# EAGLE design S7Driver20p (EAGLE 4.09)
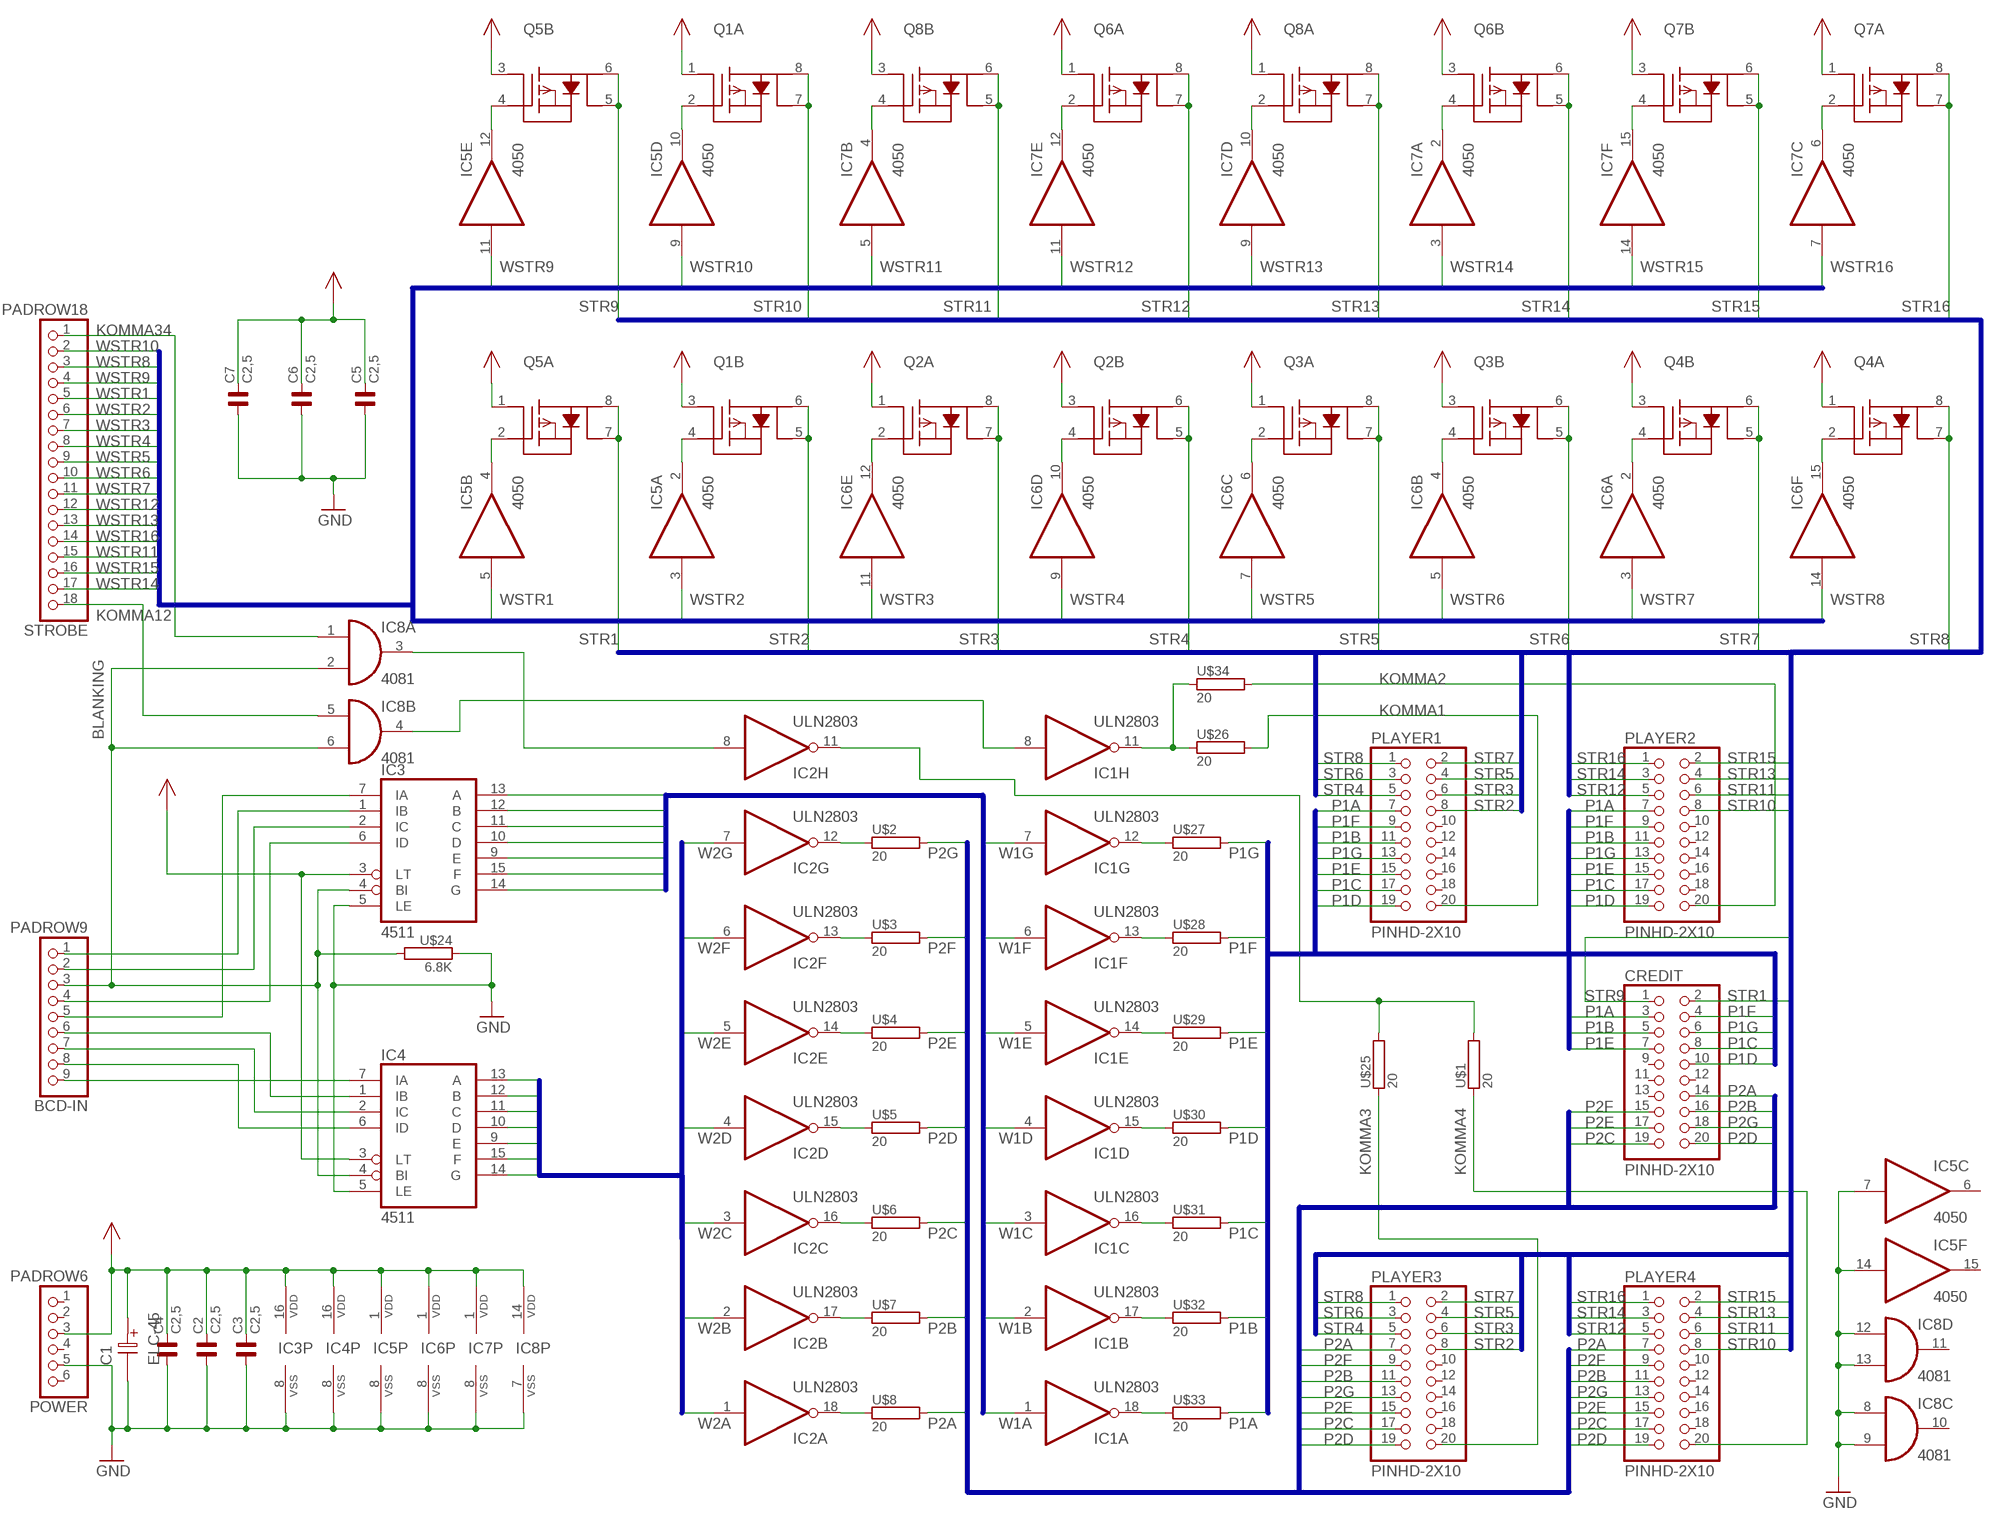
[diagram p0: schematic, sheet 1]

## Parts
BCD-IN  PADROW9  [PLATINE9]
C1  ELC-45  [E-45]
C2  C2,5  [C5B2,5]
C3  C2,5  [C5B2,5]
C4  C2,5  [C5B2,5]
C5  C2,5  [C5B2,5]
C6  C2,5  [C5B2,5]
C7  C2,5  [C5B2,5]
CREDIT  PINHD-2X10  [2X10]
IC1  ULN2803  [DIL18]
IC2  ULN2803  [DIL18]
IC3  4511  [DIL16]
IC4  4511  [DIL16]
IC5  4050  [DIL16]
IC6  4050  [DIL16]
IC7  4050  [DIL16]
IC8  4081  [DIL14]
PLAYER1  PINHD-2X10  [2X10]
PLAYER2  PINHD-2X10  [2X10]
PLAYER3  PINHD-2X10  [2X10]
PLAYER4  PINHD-2X10  [2X10]
POWER  PADROW6  [PLATINE6]
Q1  IRF7316  [SO-8]
Q2  IRF7316  [SO-8]
Q3  IRF7316  [SO-8]
Q4  IRF7316  [SO-8]
Q5  IRF7316  [SO-8]
Q6  IRF7316  [SO-8]
Q7  IRF7316  [SO-8]
Q8  IRF7316  [SO-8]
STROBE  PADROW18  [PLTINE18]
U$1  20  R1206  [0207/10]
U$2  20  R1206@2  [0207/15A]
U$3  20  R1206@2  [0207/15A]
U$4  20  R1206@2  [0207/15A]
U$5  20  R1206@2  [0207/15A]
U$6  20  R1206@2  [0207/15A]
U$7  20  R1206@2  [0207/15A]
U$8  20  R1206@2  [0207/15A]
U$24  6.8K  R1206@3  [0207/12A]
U$25  20  R1206  [0207/10]
U$26  20  R1206  [0207/10]
U$27  20  R1206  [0207/10]
U$28  20  R1206  [0207/10]
U$29  20  R1206  [0207/10]
U$30  20  R1206  [0207/10]
U$31  20  R1206  [0207/10]
U$32  20  R1206  [0207/10]
U$33  20  R1206  [0207/10]
U$34  20  R1206  [0207/10]

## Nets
BLANKING: BCD-IN.3 IC3.4(BI) IC4.4(BI) IC8.2(A:I1) IC8.6(B:I1) U$24.2
GND: C1.2 C2.1 C3.1 C4.1 C5.1 C6.1 C7.1 IC3.5(LE) IC3.8(VSS) IC4.5(LE) IC4.8(VSS) IC5.7(C:I) IC5.8(P:VSS) IC5.14(F:I) IC6.8(P:VSS) IC7.8(P:VSS) IC8.7(P:VSS) IC8.8(C:I0) IC8.9(C:I1) IC8.12(D:I0) IC8.13(D:I1) POWER.5 U$24.1
KOMMA1: PLAYER1.20 U$26.2
KOMMA2: PLAYER2.20 U$34.2
KOMMA3: PLAYER3.20 U$25.1
KOMMA4: PLAYER4.20 U$1.1
KOMMA12: IC8.5(B:I0) STROBE.18
KOMMA34: IC8.1(A:I0) STROBE.1
N$1: IC1.11(H:O) U$26.1 U$34.1
N$2: IC1.12(G:O) U$27.1
N$3: IC1.13(F:O) U$28.1
N$4: IC1.14(E:O) U$29.1
N$5: IC1.15(D:O) U$30.1
N$6: IC1.16(C:O) U$31.1
N$7: IC1.17(B:O) U$32.1
N$8: IC1.18(A:O) U$33.1
N$9: IC2.11(H:O) U$1.2 U$25.2
N$10: IC2.14(E:O) U$4.1
N$11: IC2.15(D:O) U$5.1
N$12: IC2.16(C:O) U$6.1
N$13: IC2.17(B:O) U$7.1
N$14: IC2.18(A:O) U$8.1
N$15: IC2.12(G:O) U$2.1
N$16: IC2.13(F:O) U$3.1
N$17: BCD-IN.2 IC3.2(IC)
N$18: BCD-IN.4 IC3.6(ID)
N$19: BCD-IN.5 IC3.7(IA)
N$20: BCD-IN.6 IC4.1(IB)
N$21: BCD-IN.7 IC4.2(IC)
N$22: BCD-IN.8 IC4.6(ID)
N$23: BCD-IN.9 IC4.7(IA)
N$24: IC1.8(H:I) IC8.4(B:O)
N$25: BCD-IN.1 IC3.1(IB)
N$26: IC5.12(E:O) Q5.4
N$27: IC7.2(A:O) Q6.4
N$28: IC5.10(D:O) Q1.2
N$30: IC7.15(F:O) Q7.4
N$31: IC7.4(B:O) Q8.4
N$33: IC7.12(E:O) Q6.2
N$34: IC5.4(B:O) Q5.2
N$35: IC5.2(A:O) Q1.4
N$36: IC6.12(E:O) Q2.2
N$37: IC7.6(C:O) Q7.2
N$38: IC6.10(D:O) Q2.4
N$39: IC7.10(D:O) Q8.2
N$40: IC6.6(C:O) Q3.2
N$44: IC6.4(B:O) Q3.4
N$46: IC6.2(A:O) Q4.4
N$48: IC2.8(H:I) IC8.3(A:O)
N$49: IC6.15(F:O) Q4.2
P1A: CREDIT.3 PLAYER1.7 PLAYER2.7 U$33.2
P1B: CREDIT.5 PLAYER1.11 PLAYER2.11 U$32.2
P1C: CREDIT.8 PLAYER1.17 PLAYER2.17 U$31.2
P1D: CREDIT.10 PLAYER1.19 PLAYER2.19 U$30.2
P1E: CREDIT.7 PLAYER1.15 PLAYER2.15 U$29.2
P1F: CREDIT.4 PLAYER1.9 PLAYER2.9 U$28.2
P1G: CREDIT.6 PLAYER1.13 PLAYER2.13 U$27.2
P2A: CREDIT.14 PLAYER3.7 PLAYER4.7 U$8.2
P2B: CREDIT.16 PLAYER3.11 PLAYER4.11 U$7.2
P2C: CREDIT.19 PLAYER3.17 PLAYER4.17 U$6.2
P2D: CREDIT.20 PLAYER3.19 PLAYER4.19 U$5.2
P2E: CREDIT.17 PLAYER3.15 PLAYER4.15 U$4.2
P2F: CREDIT.15 PLAYER3.9 PLAYER4.9 U$3.2
P2G: CREDIT.18 PLAYER3.13 PLAYER4.13 U$2.2
STR1: CREDIT.2 Q5.7 Q5.8
STR2: PLAYER1.8 PLAYER3.8 Q1.5 Q1.6
STR3: PLAYER1.6 PLAYER3.6 Q2.7 Q2.8
STR4: PLAYER1.5 PLAYER3.5 Q2.5 Q2.6
STR5: PLAYER1.4 PLAYER3.4 Q3.7 Q3.8
STR6: PLAYER1.3 PLAYER3.3 Q3.5 Q3.6
STR7: PLAYER1.2 PLAYER3.2 Q4.5 Q4.6
STR8: PLAYER1.1 PLAYER3.1 Q4.7 Q4.8
STR9: CREDIT.1 Q5.5 Q5.6
STR10: PLAYER2.8 PLAYER4.8 Q1.7 Q1.8
STR11: PLAYER2.6 PLAYER4.6 Q8.5 Q8.6
STR12: PLAYER2.5 PLAYER4.5 Q6.7 Q6.8
STR13: PLAYER2.4 PLAYER4.4 Q8.7 Q8.8
STR14: PLAYER2.3 PLAYER4.3 Q6.5 Q6.6
STR15: PLAYER2.2 PLAYER4.2 Q7.5 Q7.6
STR16: PLAYER2.1 PLAYER4.1 Q7.7 Q7.8
VCC: C1.1 C2.2 C3.2 C4.2 C5.2 C6.2 C7.2 IC3.3(LT) IC3.16(VDD) IC4.3(LT) IC4.16(VDD) IC5.1(P:VDD) IC6.1(P:VDD) IC7.1(P:VDD) IC8.14(P:VDD) POWER.3 Q1.1 Q1.3 Q2.1 Q2.3 Q3.1 Q3.3 Q4.1 Q4.3 Q5.1 Q5.3 Q6.1 Q6.3 Q7.1 Q7.3 Q8.1 Q8.3
W1A: IC1.1(A:I) IC3.13(A)
W1B: IC1.2(B:I) IC3.12(B)
W1C: IC1.3(C:I) IC3.11(C)
W1D: IC1.4(D:I) IC3.10(D)
W1E: IC1.5(E:I) IC3.9(E)
W1F: IC1.6(F:I) IC3.15(F)
W1G: IC1.7(G:I) IC3.14(G)
W2A: IC2.1(A:I) IC4.13(A)
W2B: IC2.2(B:I) IC4.12(B)
W2C: IC2.3(C:I) IC4.11(C)
W2D: IC2.4(D:I) IC4.10(D)
W2E: IC2.5(E:I) IC4.9(E)
W2F: IC2.6(F:I) IC4.15(F)
W2G: IC2.7(G:I) IC4.14(G)
WSTR1: IC5.5(B:I) STROBE.5
WSTR2: IC5.3(A:I) STROBE.6
WSTR3: IC6.11(E:I) STROBE.7
WSTR4: IC6.9(D:I) STROBE.8
WSTR5: IC6.7(C:I) STROBE.9
WSTR6: IC6.5(B:I) STROBE.10
WSTR7: IC6.3(A:I) STROBE.11
WSTR8: IC6.14(F:I) STROBE.3
WSTR9: IC5.11(E:I) STROBE.4
WSTR10: IC5.9(D:I) STROBE.2
WSTR11: IC7.5(B:I) STROBE.15
WSTR12: IC7.11(E:I) STROBE.12
WSTR13: IC7.9(D:I) STROBE.13
WSTR14: IC7.3(A:I) STROBE.17
WSTR15: IC7.14(F:I) STROBE.16
WSTR16: IC7.7(C:I) STROBE.14
Unconnected: CREDIT.9 CREDIT.11 CREDIT.12 CREDIT.13 IC1.10(CLAMP:CLAMP) IC2.10(CLAMP:CLAMP) IC5.6(C:O) IC5.15(F:O) IC8.10(C:O) IC8.11(D:O) PLAYER1.10 PLAYER1.12 PLAYER1.14 PLAYER1.16 PLAYER1.18 PLAYER2.10 PLAYER2.12 PLAYER2.14 PLAYER2.16 PLAYER2.18 PLAYER3.10 PLAYER3.12 PLAYER3.14 PLAYER3.16 PLAYER3.18 PLAYER4.10 PLAYER4.12 PLAYER4.14 PLAYER4.16 PLAYER4.18 POWER.1 POWER.2 POWER.4 POWER.6

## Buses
W2:W2A,W2B,W2C,W2D,W2E,W2F,W2G
W1:W1A,W1B,W1C,W1D,W1E,W1F,W1G
P1:P1A,P1B,P1C,P1D,P1E,P1F,P1G
P2:P2A,P2B,P2C,P2D,P2E,P2F,P2G
WSTR:WSTR1,WSTR2,WSTR3,WSTR4,WSTR5,WSTR6,WSTR7,WSTR8,WSTR9,WSTR10,WSTR11,WSTR12,WSTR13,WSTR14,WSTR15,WSTR16
STR:STR1,STR2,STR3,STR4,STR5,STR6,STR7,STR8,STR9,STR10,STR11,STR12,STR13,STR14,STR15,STR16

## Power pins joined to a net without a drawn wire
GND: IC1.9(GND:GND) IC2.9(GND:GND)

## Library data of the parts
BCD-IN = SPECIAL:PADROW9
C1 = DISCRETE:ELC-45
C2-C7 = CAP:C2,5
CREDIT PLAYER1-PLAYER4 = PINHEAD:PINHD-2X10
IC1 IC2 = SPECIAL:ULN2803
IC3 IC4 = 45XXSMD:4511
IC5-IC7 = 40XX:4050
IC8 = 40XXSMD:4081
POWER = SPECIAL:PADROW6
Q1-Q8 = Fari:IRF7316
STROBE = SPECIAL:PADROW18
U$1 U$25 U$34 = SPECIAL:R1206
U$2-U$8 = R:R1206@2
U$24 = R:R1206@3
U$26-U$33 = R:R1206

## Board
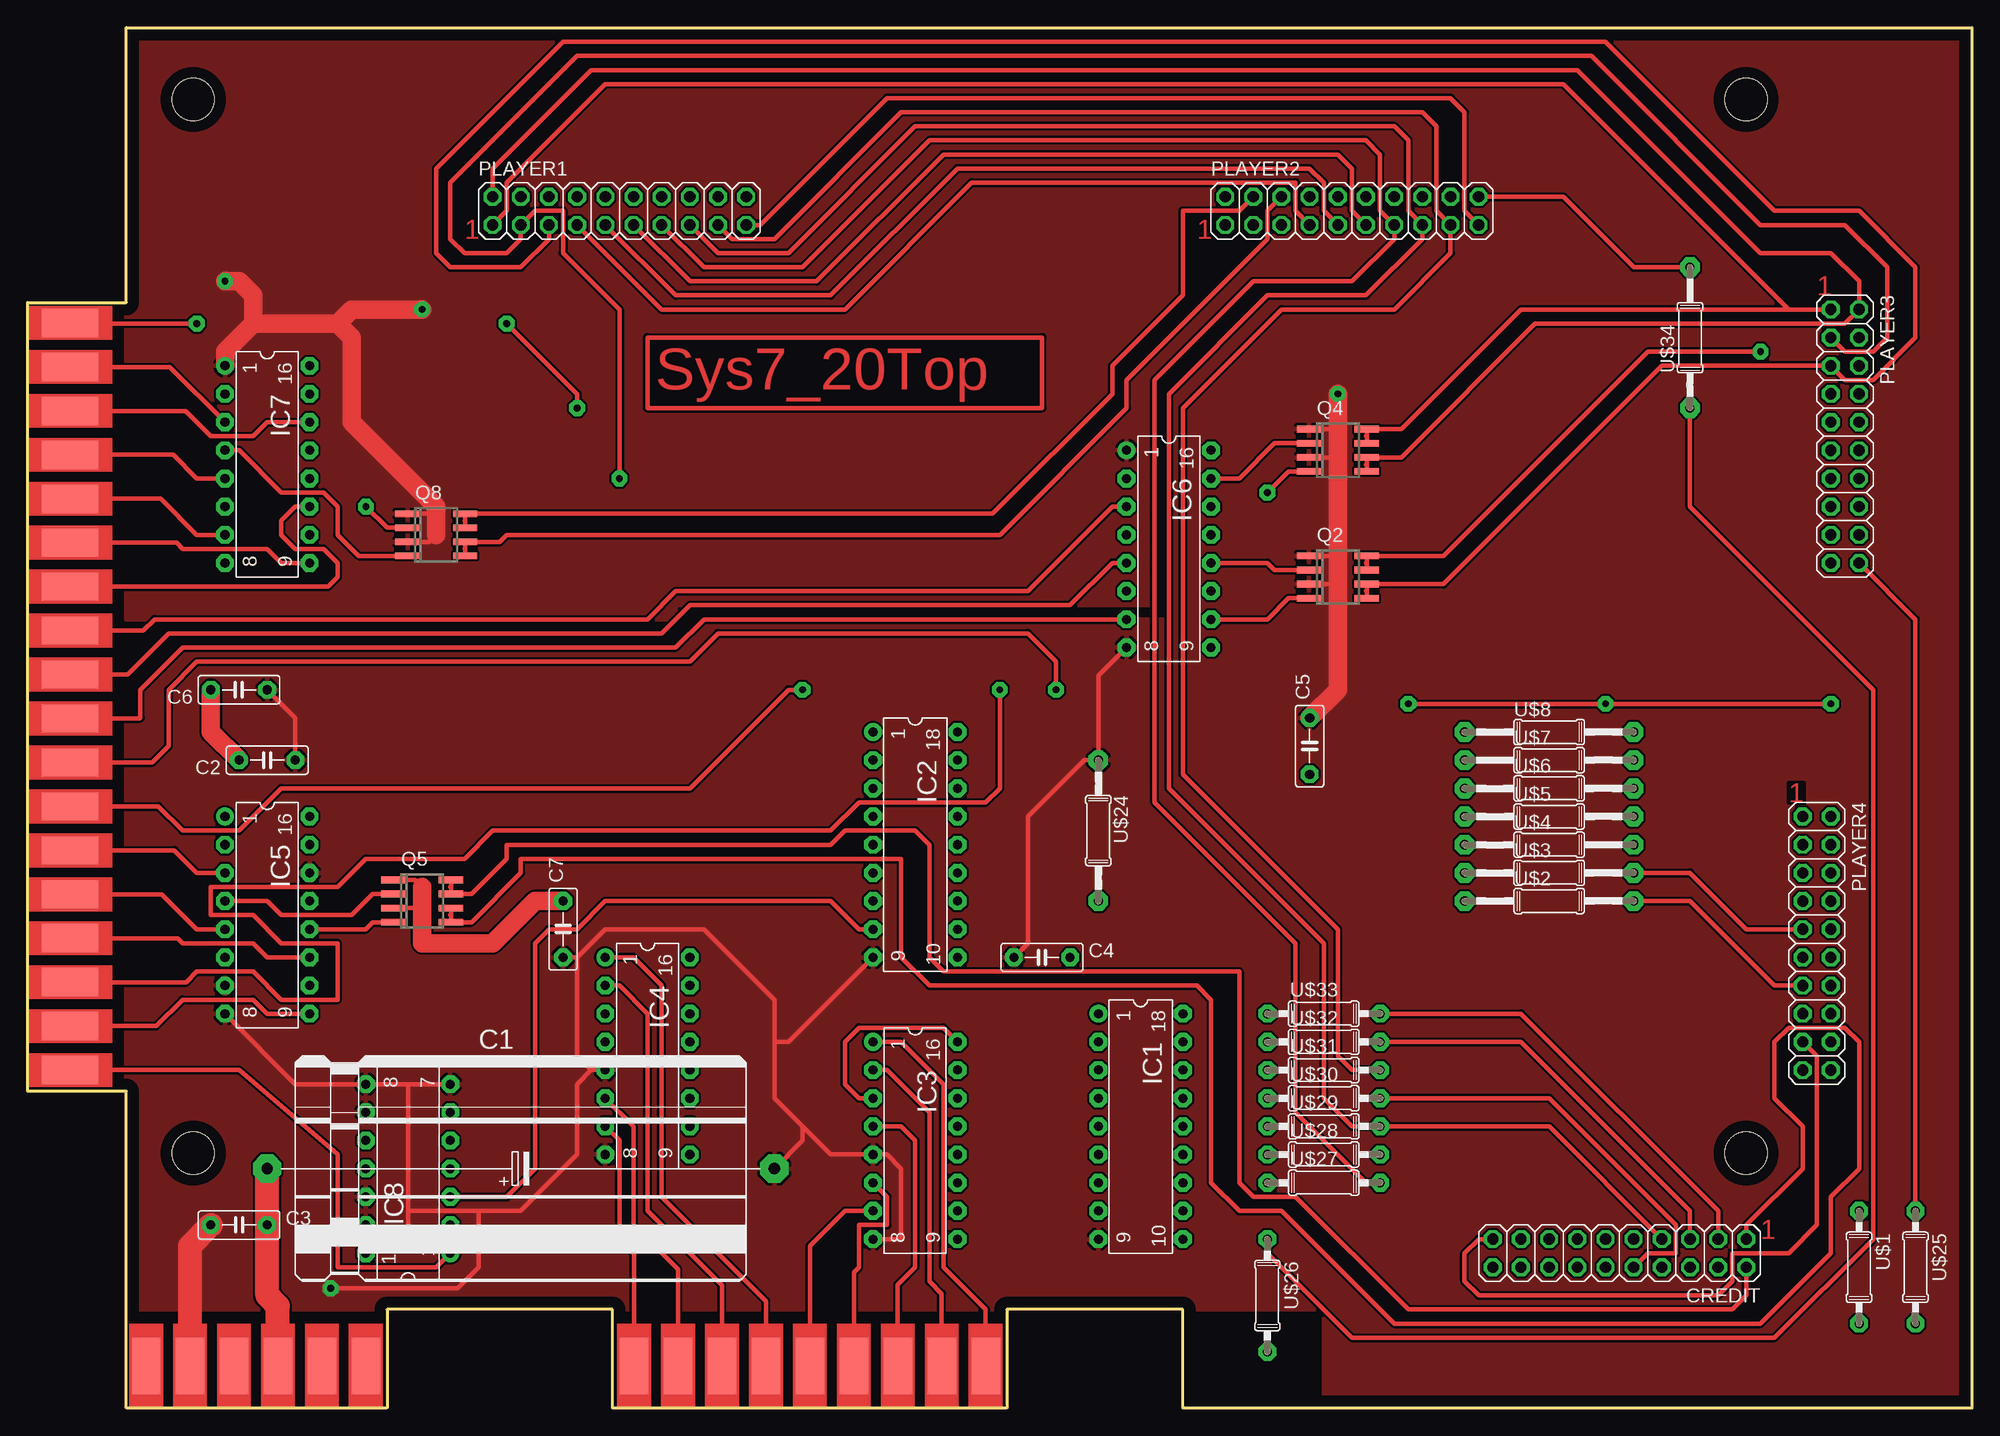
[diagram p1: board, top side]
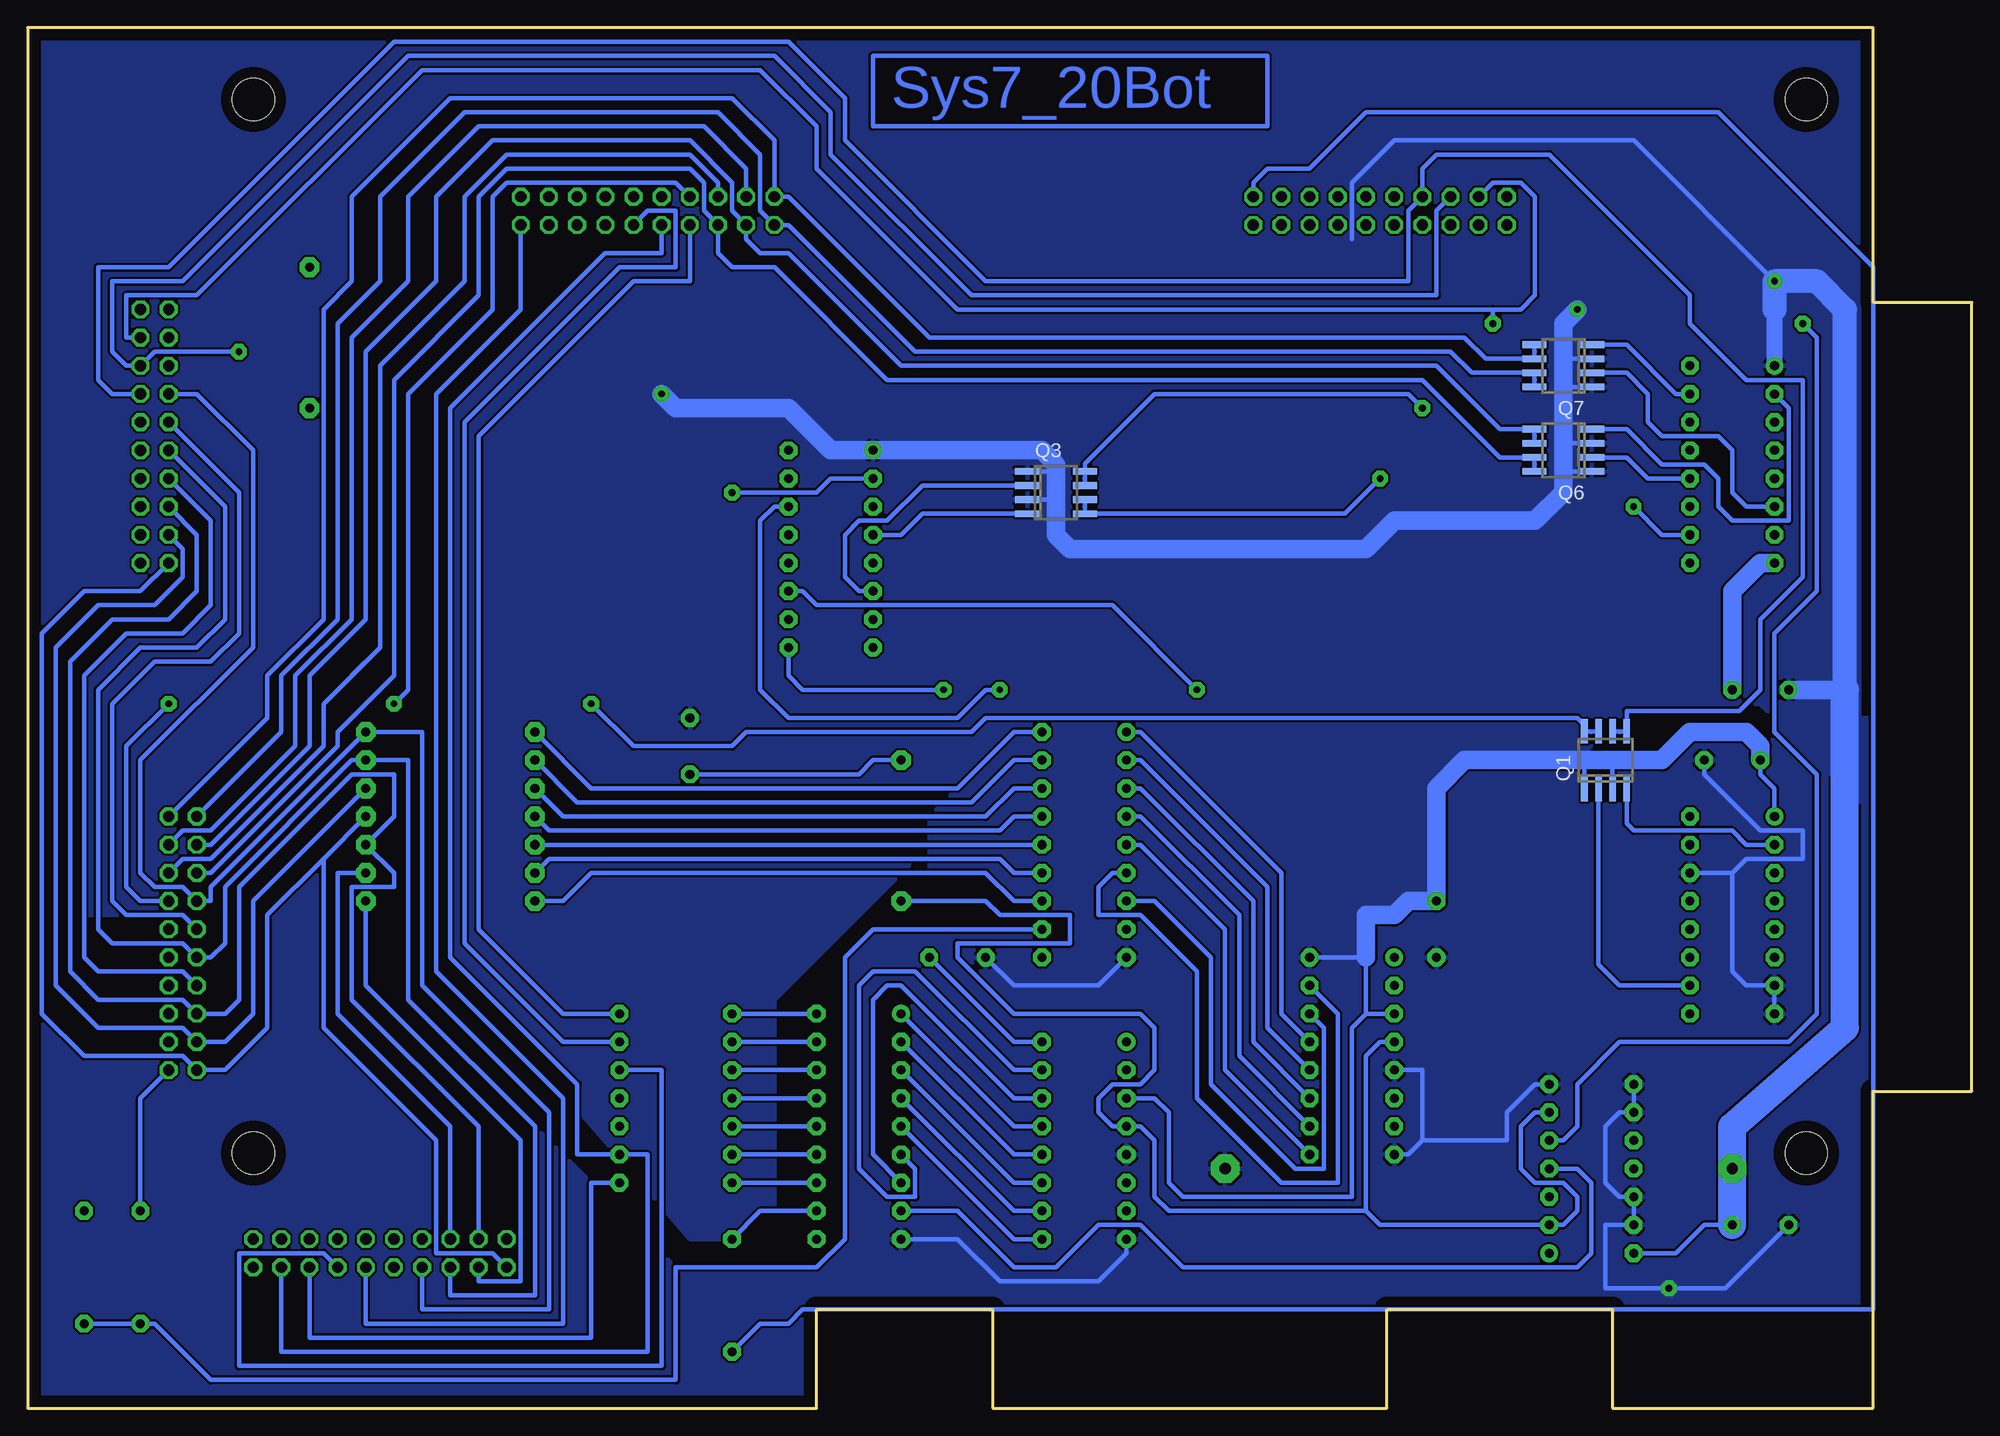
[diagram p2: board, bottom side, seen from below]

Size 175.26 x 124.46 mm. Coordinates in mm from the lower left corner, seen from the top.
Outline: 8.89,0 8.89,28.57 0,28.57 0,99.69 8.89,99.69 8.89,124.46 175.26,124.46 175.26,0 104.14,0 104.14,8.89 88.27,8.89 88.27,0 52.7,0 52.7,8.89 32.38,8.89 32.38,0 8.89,0
Copper layers used: Top, Bottom
Holes 3.81 mm at 14.92,23 154.92,23 154.92,118 14.92,118

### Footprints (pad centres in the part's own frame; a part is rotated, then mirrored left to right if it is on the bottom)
PLATINE9 = smd 2.54 x 5.08: 1 0,0; 2 3.962,0; 3 7.925,0; 4 11.887,0; 5 15.85,0; 6 19.812,0; 7 23.774,0; 8 27.737,0; 9 31.699,0
E-45 = drill 1.016 pad 2.54 octagon: 1 0,0; 2 45.72,0
C5B2,5 = drill 0.813 pad 1.6 octagon: 1 -2.54,0; 2 2.54,0
2X10 = drill 1.016 pad 1.6 octagon: 1 -11.43,-1.27; 2 -11.43,1.27; 3 -8.89,-1.27; 4 -8.89,1.27; 5 -6.35,-1.27; 6 -6.35,1.27; 7 -3.81,-1.27; 8 -3.81,1.27; 9 -1.27,-1.27; 10 -1.27,1.27; 11 1.27,-1.27; 12 1.27,1.27; 13 3.81,-1.27; 14 3.81,1.27; 15 6.35,-1.27; 16 6.35,1.27; 17 8.89,-1.27; 18 8.89,1.27; 19 11.43,-1.27; 20 11.43,1.27
DIL18 = drill 0.813 pad 1.6 round: 1 -10.16,-3.81 | drill 0.813 pad 1.6 octagon: 2 -7.62,-3.81; 3 -5.08,-3.81; 4 -2.54,-3.81; 5 0,-3.81; 6 2.54,-3.81; 7 5.08,-3.81; 8 7.62,-3.81; 9 10.16,-3.81; 10 10.16,3.81; 11 7.62,3.81; 12 5.08,3.81; 13 2.54,3.81; 14 0,3.81; 15 -2.54,3.81; 16 -5.08,3.81; 17 -7.62,3.81; 18 -10.16,3.81
DIL16 = drill 0.813 pad 1.6 round: 1 -8.89,-3.81 | drill 0.813 pad 1.6 octagon: 2 -6.35,-3.81; 3 -3.81,-3.81; 4 -1.27,-3.81; 5 1.27,-3.81; 6 3.81,-3.81; 7 6.35,-3.81; 8 8.89,-3.81; 9 8.89,3.81; 10 6.35,3.81; 11 3.81,3.81; 12 1.27,3.81; 13 -1.27,3.81; 14 -3.81,3.81; 15 -6.35,3.81; 16 -8.89,3.81
DIL14 = drill 0.813 pad 1.6 round: 1 -7.62,-3.81 | drill 0.813 pad 1.6 octagon: 2 -5.08,-3.81; 3 -2.54,-3.81; 4 0,-3.81; 5 2.54,-3.81; 6 5.08,-3.81; 7 7.62,-3.81; 8 7.62,3.81; 9 5.08,3.81; 10 2.54,3.81; 11 0,3.81; 12 -2.54,3.81; 13 -5.08,3.81; 14 -7.62,3.81
PLATINE6 = smd 2.54 x 5.08: 1 0,0; 2 3.962,0; 3 7.925,0; 4 11.887,0; 5 15.85,0; 6 19.812,0
SO-8 = smd 0.6 x 2.2: 1 -1.905,-2.6; 2 -0.635,-2.6; 3 0.635,-2.6; 4 1.905,-2.6; 5 1.905,2.6; 6 0.635,2.6; 7 -0.635,2.6; 8 -1.905,2.6
PLTINE18 = smd 2.54 x 5.08: 1 0,0; 2 3.962,0; 3 7.925,0; 4 11.887,0; 5 15.85,0; 6 19.812,0; 7 23.774,0; 8 27.737,0; 9 31.699,0; 10 35.662,0; 11 39.624,0; 12 43.586,0; 13 47.549,0; 14 51.511,0; 15 55.474,0; 16 59.436,0; 17 63.398,0; 18 67.361,0
0207/10 = drill 0.813 pad 1.6 octagon: 1 -5.08,0; 2 5.08,0
0207/15A = drill 0.813 pad 1.778 octagon: 1 -7.62,0; 2 7.62,0
0207/12A = drill 0.813 pad 1.778 octagon: 1 -6.35,0; 2 6.35,0

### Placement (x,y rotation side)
BCD-IN  86.36,3.81 180 top
C1  21.59,21.59 0 top
C2  21.59,58.42 180 top
C3  19.05,16.51 0 top
C4  91.44,40.64 0 top
C5  115.57,59.69 90 top
C6  19.05,64.77 180 top
C7  48.26,43.18 90 top
CREDIT  143.51,13.97 180 top
IC1  100.33,25.4 270 top
IC2  80.01,50.8 270 top
IC3  80.01,24.13 270 top
IC4  55.88,31.75 270 top
IC5  21.59,44.45 270 top
IC6  102.87,77.47 270 top
IC7  21.59,85.09 270 top
IC8  34.29,21.59 90 top
PLAYER1  53.34,107.95 0 top
PLAYER2  119.38,107.95 0 top
PLAYER3  163.83,87.63 270 top
PLAYER4  161.29,41.91 270 top
POWER  30.48,3.81 180 top
Q1  33.02,58.42 0 bottom
Q2  118.11,74.93 270 top
Q3  82.55,82.55 270 bottom
Q4  118.11,86.36 270 top
Q5  35.56,45.72 270 top
Q6  36.83,86.36 90 bottom
Q7  36.83,93.98 90 bottom
Q8  36.83,78.74 270 top
STROBE  3.81,30.48 90 top
U$1  165.1,12.7 270 top
U$2  137.16,45.72 0 top
U$3  137.16,48.26 0 top
U$4  137.16,50.8 0 top
U$5  137.16,53.34 0 top
U$6  137.16,55.88 0 top
U$7  137.16,58.42 0 top
U$8  137.16,60.96 0 top
U$24  96.52,52.07 270 top
U$25  170.18,12.7 270 top
U$26  111.76,10.16 270 top
U$27  116.84,20.32 0 top
U$28  116.84,22.86 0 top
U$29  116.84,25.4 0 top
U$30  116.84,27.94 0 top
U$31  116.84,30.48 0 top
U$32  116.84,33.02 0 top
U$33  116.84,35.56 0 top
U$34  20  [0207/12A]  149.86,96.52 90 top

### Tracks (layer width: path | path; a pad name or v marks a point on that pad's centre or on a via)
BLANKING
  Top 0.406: IC3.4 78.74,25.4 80.01,24.13 80.01,12.7 78.44,11.12 BCD-IN.3
  Bottom 0.406: IC4.4 53.34,33.02 54.61,31.75 54.61,17.78 | 54.61,17.78 72.39,17.78 73.66,19.05 73.66,24.13 74.93,25.4 IC3.4 77.47,25.4 78.74,26.67 78.74,27.94 77.47,29.21 74.93,29.21 73.66,30.48 73.66,34.29 74.93,35.56 86.36,35.56 91.44,40.64 91.44,41.91 81.28,41.91 81.28,44.45 87.63,44.45 88.9,45.72 U$24.2 | 54.61,17.78 53.34,16.51 IC8.2 36.83,16.51 35.56,17.78 35.56,19.05 36.83,20.32 39.37,20.32 40.64,21.59 40.64,25.4 39.37,26.67 IC8.6
GND  (via drill 0.61 pad 1.42)
  Top 0.406: 69.85,25.4 67.31,27.94 67.31,33.02 | 69.85,25.4 72.39,22.86 IC3.5 77.47,22.86 78.74,21.59 78.74,15.24 IC3.8 | 67.31,33.02 67.31,36.83 60.96,43.18 52.07,43.18 49.53,40.64 | 49.53,40.64 49.53,31.75 50.8,30.48 | 50.8,30.48 IC4.5 | IC5.8 24.13,29.21 IC8.8 34.29,29.21 | 34.29,29.21 IC8.7 | 67.31,33.02 68.58,33.02 IC2.9 | IC6.8 96.52,66.04 U$24.1 95.25,58.42 90.17,53.34 90.17,41.91 C4.1 | 49.53,40.64 C7.1 | 50.8,30.48 49.53,29.21 49.53,22.86 44.45,17.78 40.64,17.78 | 40.64,15.24 40.64,17.78 | 40.64,15.24 35.56,15.24 34.29,16.51 34.29,17.78 | 34.29,17.78 34.29,29.21 | 40.64,17.78 34.29,17.78 | v27.3,10.79 38.73,10.79 40.64,12.7 40.64,15.24 | C2.1 24.13,62.23 C6.1 | C1.2 69.85,24.13 69.85,25.4
  Top 2.184: POWER.5 14.63,14.63 C3.1
  Bottom 0.406: IC8.8 IC8.9 31.75,26.67 33.02,25.4 33.02,20.32 31.75,19.05 IC8.12 IC8.13 33.02,16.51 33.02,10.79 v27.3,10.79 22.23,10.79 C3.1 | IC8.7 39.37,29.21 41.91,26.67 41.91,24.13 49.53,24.13 | IC4.5 49.53,30.48 49.53,24.13 | IC4.8 50.8,22.86 49.53,24.13 | IC3.8 76.2,13.97 78.74,11.43 87.63,11.43 91.44,15.24 IC1.9 | U$24.1 99.06,58.42 100.33,57.15 C5.1 | IC2.9 78.74,38.1 86.36,38.1 C4.1 | IC5.8 IC5.7 20.32,38.1 21.59,39.37 21.59,48.26 | 21.59,48.26 IC5.14 | C2.1 24.13,57.15 19.05,52.07 15.24,52.07 15.24,49.53 20.32,49.53 21.59,48.26
  Bottom 1.676: IC7.8 19.05,76.2 21.59,73.66 C6.1
  pour Top: 8.89,8.89 8.89,69.85 59.69,69.85 59.69,71.12 104.14,71.12 104.14,54.61 116.84,41.91 116.84,30.48 135.89,30.48 148.59,17.78 148.59,8.89 149.86,8.89
  pour Bottom: 8.89,8.89 8.89,62.23 29.21,62.23 33.02,58.42 45.72,58.42 48.26,55.88 48.26,45.72 54.61,44.45 54.61,41.91 62.23,41.91 62.23,48.26 76.2,62.23 85.09,62.23 93.98,53.34 93.98,43.18 102.87,43.18 110.49,35.56 110.49,12.7 116.84,12.7 147.32,43.18 147.32,49.53 148.59,50.8 157.48,43.18 161.29,39.37 173.99,39.37 173.99,0 104.14,0 104.14,8.89
KOMMA1
  Bottom 0.406: U$26.2 109.22,7.62 106.68,7.62 105.41,8.89 8.89,8.89 8.89,102.87 22.86,116.84 54.61,116.84 59.69,111.76 63.5,111.76 64.77,110.49 PLAYER1.20
KOMMA2
  Top 0.406: PLAYER2.20 138.43,109.22 144.78,102.87 U$34.2
KOMMA3
  Top 0.406: PLAYER3.20 170.18,71.12 U$25.1
KOMMA4
  Bottom 0.406: U$1.1 165.1,27.94 PLAYER4.20
KOMMA12  (via drill 0.61 pad 1.42)
  Top 0.406: STROBE.18 5.08,97.79 v15.24,97.79
  Bottom 0.406: IC8.5 36.83,24.13 35.56,25.4 35.56,29.21 31.75,33.02 16.51,33.02 13.97,35.56 13.97,57.15 17.78,60.96 17.78,69.85 13.97,73.66 13.97,96.52 v15.24,97.79
KOMMA34
  Top 0.406: STROBE.1 19.05,30.48 27.94,22.86 27.94,12.7 36.83,12.7 IC8.1
N$1
  Top 0.406: U$26.1 111.76,13.97 119.38,6.35 157.48,6.35 166.37,15.24 166.37,64.77 149.86,81.28 U$34.1
  Bottom 0.406: IC1.11 109.22,17.78 U$26.1
N$2
  Bottom 0.406: IC1.12 U$27.1
N$3
  Bottom 0.406: IC1.13 U$28.1
N$4
  Bottom 0.406: IC1.14 U$29.1
N$5
  Bottom 0.406: IC1.15 U$30.1
N$6
  Bottom 0.406: IC1.16 U$31.1
N$7
  Bottom 0.406: IC1.17 U$32.1
N$8
  Bottom 0.406: IC1.18 U$33.1
N$9
  Bottom 0.406: U$25.2 U$1.2 163.83,7.62 158.75,2.54 116.84,2.54 116.84,12.7 104.14,12.7 101.6,15.24 101.6,40.64 99.06,43.18 IC2.11
N$10
  Bottom 0.406: IC2.14 U$4.1
N$11
  Bottom 0.406: IC2.15 86.36,53.34 87.63,52.07 128.27,52.07 U$5.1
N$12
  Bottom 0.406: IC2.16 86.36,55.88 88.9,53.34 127,53.34 U$6.1
N$13
  Bottom 0.406: IC2.17 86.36,58.42 90.17,54.61 125.73,54.61 U$7.1
N$14
  Bottom 0.406: IC2.18 86.36,60.96 91.44,55.88 124.46,55.88 U$8.1
N$15
  Bottom 0.406: IC2.12 86.36,45.72 88.9,48.26 124.46,48.26 127,45.72 U$2.1
N$16
  Bottom 0.406: IC2.13 86.36,48.26 87.63,49.53 128.27,49.53 U$3.1
N$17
  Top 0.406: BCD-IN.2 82.4,10.31 81.28,11.43 81.28,26.67 77.47,30.48 IC3.2
N$18
  Top 0.406: IC3.6 77.47,19.05 77.47,16.51 74.93,16.51 74.93,12.7 74.47,12.24 BCD-IN.4
N$19
  Top 0.406: BCD-IN.5 70.51,14.63 73.66,17.78 IC3.7
N$20
  Top 0.406: BCD-IN.6 66.55,9.65 57.15,19.05 57.15,38.1 54.61,40.64 IC4.1
N$21
  Top 0.406: BCD-IN.7 62.59,11.07 55.88,17.78 55.88,35.56 53.34,38.1 IC4.2
N$22
  Top 0.406: BCD-IN.8 58.62,12.5 54.61,16.51 54.61,25.4 IC4.6
N$23
  Top 0.406: BCD-IN.9 54.66,13.92 53.34,15.24 53.34,24.13 IC4.7
N$24
  Bottom 0.406: IC8.4 35.56,21.59 34.29,20.32 34.29,13.97 35.56,12.7 71.12,12.7 74.93,16.51 78.74,16.51 82.55,12.7 86.36,12.7 91.44,17.78 IC1.8
N$25
  Top 0.406: BCD-IN.1 86.36,8.89 82.55,12.7 82.55,29.21 78.74,33.02 IC3.1
N$26
  Top 0.406: Q5.4 31.11,43.81 30.48,43.18 IC5.12
N$27
  Bottom 0.406: Q6.4 31.11,88.27 27.94,85.09 24.13,85.09 22.86,83.82 22.86,81.28 21.59,80.01 16.51,80.01 16.51,90.17 IC7.2
N$28
  Bottom 0.406: Q1.2 33.66,40.01 31.75,38.1 IC5.10
N$30
  Bottom 0.406: IC7.15 26.67,91.44 31.11,95.89 Q7.4
N$31
  Top 0.406: Q8.4 29.84,76.83 27.94,78.74 27.94,81.28 26.67,82.55 22.86,82.55 19.05,86.36 IC7.4
N$33
  Bottom 0.406: Q6.2 31.11,85.72 29.21,83.82 IC7.12
N$34
  Top 0.406: Q5.2 31.11,46.35 29.21,44.45 22.86,44.45 21.59,45.72 IC5.4
N$35
  Bottom 0.406: Q1.4 31.11,52.7 30.48,52.07 21.59,52.07 20.32,50.8 IC5.2
N$36
  Top 0.406: Q2.2 112.39,75.56 111.76,76.2 IC6.12
N$37
  Bottom 0.406: IC7.6 20.32,81.28 21.59,82.55 21.59,86.36 22.86,87.63 27.94,87.63 29.21,88.9 29.21,91.44 31.11,93.34 Q7.2
N$38
  Top 0.406: Q2.4 113.67,73.03 111.76,71.12 IC6.10
N$39  (via drill 0.61 pad 1.42)
  Top 0.406: Q8.2 32.38,79.38 v30.48,81.28
  Bottom 0.406: v30.48,81.28 27.94,78.74 IC7.10
N$40
  Bottom 0.406: Q3.2 94.61,83.19 97.79,80.01 100.33,80.01 101.6,78.74 101.6,74.93 100.33,73.66 IC6.6
N$42
  Bottom 0.406: 63.5,115.57 63.5,121.92 99.06,121.92 99.06,115.57 63.5,115.57
N$43
  Top 0.406: 55.88,90.17 55.88,96.52 91.44,96.52 91.44,90.17 55.88,90.17
N$44
  Bottom 0.406: Q3.4 94.61,80.64 96.52,78.74 IC6.4
N$46  (via drill 0.61 pad 1.42)
  Top 0.406: Q4.4 113.67,84.45 v111.76,82.55
  Bottom 0.406: v111.76,82.55 104.14,82.55 102.87,83.82 IC6.2
N$48
  Top 0.406: IC8.3 43.18,19.05 45.72,21.59 45.72,41.91 46.99,43.18 49.53,43.18 52.07,45.72 72.39,45.72 74.93,43.18 IC2.8
N$49
  Top 0.406: Q4.2 112.39,87 109.22,83.82 IC6.15
P1A
  Top 0.406: CREDIT.3 152.4,17.78 134.62,35.56 U$33.2 | PLAYER2.7 114.3,107.95 114.3,110.49 85.09,110.49 73.66,99.06 57.15,99.06 PLAYER1.7
  Bottom 0.406: PLAYER2.7 115.57,101.6 120.65,101.6 134.62,87.63 134.62,43.18 127,35.56 U$33.2
P1B
  Top 0.406: CREDIT.5 149.86,17.78 134.62,33.02 U$32.2 | PLAYER1.11 59.69,101.6 71.12,101.6 82.55,113.03 118.11,113.03 119.38,111.76 119.38,107.95 PLAYER2.11
  Bottom 0.406: PLAYER2.11 119.38,107.95 116.84,107.95 116.84,102.87 121.92,102.87 135.89,88.9 135.89,41.91 127,33.02 U$32.2
P1C
  Top 0.406: PLAYER1.17 63.5,105.41 67.31,105.41 78.74,116.84 125.73,116.84 127,115.57 127,107.95 PLAYER2.17 128.27,104.14 123.19,99.06 113.03,99.06 104.14,90.17 104.14,57.15 118.11,43.18 118.11,31.75 119.38,30.48 U$31.2
  Bottom 0.406: CREDIT.8 148.59,13.97 156.21,13.97 156.21,3.81 118.11,3.81 118.11,30.48 U$31.2
P1D
  Top 0.406: PLAYER2.19 129.54,107.95 129.54,116.84 128.27,118.11 77.47,118.11 66.04,106.68 PLAYER1.19 | U$30.2 137.16,27.94 148.59,16.51 148.59,13.97 146.05,13.97 CREDIT.10
  Bottom 0.406: CREDIT.10 144.78,7.62 127,7.62 127,27.94 138.43,39.37 138.43,91.44 130.81,99.06 PLAYER2.19
P1E
  Top 0.406: CREDIT.7 137.16,25.4 U$29.2 119.38,25.4 116.84,27.94 116.84,41.91 102.87,55.88 102.87,91.44 111.76,100.33 120.65,100.33 125.73,105.41 PLAYER2.15 124.46,107.95 124.46,114.3 123.19,115.57 80.01,115.57 68.58,104.14 62.23,104.14 PLAYER1.15
P1F
  Top 0.406: PLAYER2.9 116.84,107.95 116.84,110.49 115.57,111.76 83.82,111.76 72.39,100.33 58.42,100.33 PLAYER1.9
  Bottom 0.406: CREDIT.4 152.4,5.08 119.38,5.08 119.38,22.86 U$28.2 125.73,22.86 125.73,29.21 137.16,40.64 137.16,90.17 123.19,104.14 118.11,104.14 PLAYER2.9
P1G
  Top 0.406: PLAYER1.13 60.96,102.87 69.85,102.87 81.28,114.3 120.65,114.3 121.92,113.03 121.92,107.95 PLAYER2.13 123.19,105.41 119.38,101.6 110.49,101.6 101.6,92.71 101.6,54.61 114.3,41.91 114.3,26.67 120.65,20.32 U$27.2
  Bottom 0.406: U$27.2 124.46,20.32 124.46,6.35 149.86,6.35 CREDIT.6
P2A
  Bottom 0.406: CREDIT.14 139.7,8.89 128.27,8.89 128.27,26.67 139.7,38.1 139.7,60.96 U$8.2 158.75,46.99 158.75,45.72 PLAYER4.7 161.29,46.99 163.83,46.99 165.1,48.26 165.1,58.42 154.94,68.58 154.94,86.36 160.02,91.44 PLAYER3.7
P2B
  Bottom 0.406: CREDIT.16 137.16,10.16 129.54,10.16 129.54,25.4 140.97,36.83 140.97,58.42 U$7.2 146.05,58.42 157.48,46.99 157.48,41.91 158.75,40.64 PLAYER4.11 161.29,41.91 167.64,41.91 168.91,43.18 168.91,64.77 165.1,68.58 160.02,68.58 157.48,71.12 157.48,81.28 PLAYER3.11
P2C
  Top 0.406: PLAYER4.17 161.29,31.75 161.29,16.51 158.75,13.97 153.67,13.97 153.67,11.43 152.4,10.16 130.81,10.16 129.54,11.43 129.54,13.97 130.81,15.24 CREDIT.19
  Bottom 0.406: U$6.2 154.94,45.72 154.94,35.56 157.48,33.02 PLAYER4.17 161.29,34.29 168.91,34.29 172.72,38.1 172.72,68.58 168.91,72.39 163.83,72.39 161.29,74.93 161.29,77.47 PLAYER3.17
P2D
  Bottom 0.406: CREDIT.20 133.35,13.97 138.43,13.97 138.43,24.13 148.59,34.29 148.59,49.53 | 148.59,49.53 U$5.2 | PLAYER3.19 165.1,73.66 170.18,73.66 173.99,69.85 173.99,35.56 170.18,31.75 161.29,31.75 PLAYER4.19 157.48,30.48 153.67,34.29 153.67,44.45 148.59,49.53
P2E
  Bottom 0.406: CREDIT.17 134.62,25.4 146.05,36.83 146.05,46.99 142.24,46.99 142.24,48.26 U$4.2 142.24,53.34 142.24,57.15 146.05,57.15 156.21,46.99 156.21,36.83 157.48,35.56 PLAYER4.15 161.29,36.83 168.91,36.83 171.45,39.37 171.45,67.31 167.64,71.12 162.56,71.12 160.02,73.66 160.02,78.74 PLAYER3.15
P2F
  Top 0.406: PLAYER4.9 154.94,43.18 149.86,48.26 U$3.2
  Bottom 0.406: CREDIT.15 137.16,25.4 147.32,35.56 147.32,48.26 U$3.2 | PLAYER3.9 156.21,82.55 156.21,69.85 158.75,67.31 163.83,67.31 167.64,63.5 167.64,45.72 166.37,44.45 161.29,44.45 PLAYER4.9
P2G
  Top 0.406: U$2.2 149.86,45.72 157.48,38.1 PLAYER4.13
  Bottom 0.406: CREDIT.18 134.62,11.43 130.81,11.43 130.81,24.13 144.78,38.1 U$2.2 | PLAYER3.13 158.75,80.01 158.75,72.39 161.29,69.85 166.37,69.85 170.18,66.04 170.18,40.64 168.91,39.37 161.29,39.37 PLAYER4.13
STR1
  Top 0.406: CREDIT.2 154.94,10.16 153.67,8.89 124.46,8.89 114.3,19.05 110.49,19.05 109.22,20.32 109.22,39.37 82.55,39.37 81.28,40.64 81.28,50.8 80.01,52.07 73.66,52.07 72.39,50.8 43.18,50.8 43.18,49.53 40.01,46.35 Q5.7 38.16,46.93 38.1,46.99 38.16,47.05 Q5.8
STR2
  Bottom 0.406: PLAYER3.8 167.64,91.44 168.91,92.71 168.91,102.87 162.56,102.87 142.24,123.19 106.68,123.19 101.6,118.11 101.6,114.3 88.9,101.6 50.8,101.6 50.8,107.95 PLAYER1.8 49.53,111.76 48.26,113.03 38.1,113.03 25.4,100.33 25.4,97.79 20.32,92.71 15.24,92.71 15.24,74.93 19.05,71.12 19.05,64.77 20.95,62.87 31.11,62.87 Q1.5 31.69,61.02 31.75,60.96 31.81,61.02 Q1.6
STR3  (via drill 0.61 pad 1.42)
  Top 0.406: v156.21,95.25 146.05,95.25 127.64,76.83 Q2.8 120.71,76.26 120.65,76.2 120.71,76.14 Q2.7
  Bottom 0.406: PLAYER1.6 48.26,107.95 48.26,100.33 90.17,100.33 102.87,113.03 102.87,116.84 107.95,121.92 140.97,121.92 161.29,101.6 167.64,101.6 167.64,95.25 166.37,93.98 PLAYER3.6 163.83,95.25 v156.21,95.25
STR4
  Top 0.406: PLAYER1.5 46.99,105.41 44.45,102.87 38.1,102.87 36.83,104.14 36.83,111.76 48.26,123.19 142.24,123.19 157.48,107.95 165.1,107.95 170.18,102.87 170.18,96.52 166.37,92.71 163.83,92.71 PLAYER3.5 147.32,93.98 127.64,74.3 Q2.6 120.71,73.72 120.65,73.66 120.71,73.6 Q2.5
STR5  (via drill 0.61 pad 1.42)
  Top 0.406: v49.53,90.17 49.53,91.44 v43.18,97.79
  Bottom 0.406: PLAYER3.4 166.37,96.52 166.37,100.33 160.02,100.33 139.7,120.65 109.22,120.65 104.14,115.57 104.14,111.76 91.44,99.06 43.18,99.06 | PLAYER1.4 43.18,110.49 40.64,110.49 39.37,109.22 39.37,100.33 40.64,99.06 43.18,99.06 | v49.53,90.17 50.8,91.44 73.66,91.44 79.95,85.15 Q3.8 79.95,83.88 80.01,83.82 79.95,83.76 Q3.7 | 43.18,99.06 v43.18,97.79
STR6  (via drill 0.61 pad 1.42)
  Top 0.406: PLAYER3.3 163.83,95.25 166.37,95.25 167.64,96.52 167.64,102.87 163.83,106.68 156.21,106.68 140.97,121.92 49.53,121.92 38.1,110.49 38.1,105.41 39.37,104.14 43.18,104.14 44.45,105.41 PLAYER1.3 45.72,107.95 48.26,107.95 48.26,104.14 53.34,99.06 v53.34,83.82
  Bottom 0.406: v53.34,83.82 56.52,80.64 Q3.5 79.95,81.22 80.01,81.28 79.95,81.34 Q3.6
STR7
  Top 0.406: PLAYER1.2 41.91,111.76 50.8,120.65 139.7,120.65 156.21,104.14 162.56,104.14 165.1,101.6 PLAYER3.2 163.83,97.79 135.89,97.79 123.83,85.72 Q4.6 120.71,85.15 120.65,85.09 120.71,85.03 Q4.5
STR8
  Top 0.406: 158.75,99.06 PLAYER3.1 | 158.75,99.06 134.62,99.06 123.83,88.27 Q4.8 120.71,87.69 120.65,87.63 120.71,87.57 Q4.7 | PLAYER1.1 43.18,107.95 43.18,110.49 52.07,119.38 138.43,119.38 158.75,99.06
STR9
  Top 0.406: CREDIT.1 154.94,16.51 160.02,21.59 160.02,25.4 157.48,27.94 157.48,33.02 158.75,34.29 163.83,34.29 165.1,33.02 165.1,21.59 162.56,19.05 162.56,13.97 156.21,7.62 123.19,7.62 113.03,17.78 109.22,17.78 106.68,20.32 106.68,36.83 105.41,38.1 81.28,38.1 78.74,40.64 78.74,49.53 44.45,49.53 44.45,48.26 40.01,43.81 Q5.5 38.16,44.39 38.1,44.45 38.16,44.51 Q5.6
STR10  (via drill 0.61 pad 1.42)
  Top 0.406: v162.56,63.5 v142.24,63.5 v124.46,63.5
  Bottom 0.406: PLAYER2.8 116.84,110.49 132.08,110.49 133.35,109.22 133.35,99.06 140.97,91.44 140.97,64.77 v142.24,63.5 | PLAYER4.8 165.1,45.72 166.37,46.99 166.37,59.69 v162.56,63.5 | v124.46,63.5 120.65,59.69 111.76,59.69 110.49,60.96 90.17,60.96 88.9,62.23 35.56,62.23 34.92,61.59 Q1.8 34.35,61.02 34.29,60.96 34.23,61.02 Q1.7
STR11
  Top 0.406: PLAYER2.6 111.76,107.95 111.76,105.41 99.06,92.71 99.06,90.17 87.63,78.74 43.18,78.74 42.55,78.11 Q8.6 39.43,77.53 39.37,77.47 39.43,77.41 Q8.5
  Bottom 0.406: PLAYER4.6 161.29,49.53 158.75,49.53 148.59,59.69 148.59,63.5 143.51,68.58 | 143.51,68.58 143.51,93.98 135.89,101.6 135.89,109.22 132.08,113.03 115.57,113.03 113.03,110.49 PLAYER2.6 | 143.51,68.58 146.05,66.04
STR12
  Bottom 0.406: PLAYER4.5 158.75,48.26 147.32,59.69 147.32,60.96 142.24,66.04 142.24,92.71 134.62,100.33 134.62,109.22 132.08,111.76 115.57,111.76 114.3,110.49 114.3,107.95 PLAYER2.5 113.03,104.14 111.76,102.87 107.95,102.87 97.79,92.71 49.53,92.71 42.55,85.72 Q6.7 39.43,85.15 39.37,85.09 39.43,85.03 Q6.8
STR13
  Top 0.406: PLAYER2.4 109.22,107.95 104.14,107.95 104.14,100.33 97.79,93.98 97.79,91.44 87,80.64 Q8.8 39.43,80.07 39.37,80.01 39.43,79.95 Q8.7
  Bottom 0.406: PLAYER4.4 161.29,52.07 158.75,52.07 151.13,59.69 151.13,66.04 146.05,71.12 146.05,96.52 140.97,101.6 140.97,109.22 134.62,115.57 114.3,115.57 110.49,111.76 PLAYER2.4
STR14
  Bottom 0.406: PLAYER4.3 158.75,50.8 149.86,59.69 149.86,66.04 144.78,71.12 144.78,95.25 138.43,101.6 138.43,109.22 133.35,114.3 115.57,114.3 111.76,110.49 111.76,107.95 PLAYER2.3 110.49,105.41 109.22,104.14 106.68,104.14 96.52,93.98 48.26,93.98 42.55,88.27 Q6.5 39.43,87.69 39.37,87.63 39.43,87.57 Q6.6
STR15
  Bottom 0.406: PLAYER4.2 153.67,62.23 153.67,66.04 148.59,71.12 148.59,99.06 146.05,101.6 146.05,109.22 137.16,118.11 111.76,118.11 107.95,114.3 PLAYER2.2 106.68,109.22 93.98,96.52 45.72,96.52 43.81,94.61 Q7.6 39.43,95.19 39.37,95.25 39.43,95.31 Q7.5
STR16
  Bottom 0.406: PLAYER4.1 152.4,60.96 152.4,66.04 147.32,71.12 147.32,97.79 143.51,101.6 143.51,109.22 135.89,116.84 113.03,116.84 109.22,113.03 109.22,107.95 PLAYER2.1 106.68,106.68 95.25,95.25 46.99,95.25 45.09,93.34 Q7.7 39.43,92.77 39.37,92.71 39.43,92.65 Q7.8
VCC  (via drill 0.61 pad 1.42)
  Top 0.406: IC3.3 74.93,27.94 73.66,29.21 73.66,33.02 74.93,34.29 82.55,34.29 IC3.16 | Q5.1 34.92,47.62 35.56,46.99 | Q5.3 34.92,45.09 35.56,44.45 | Q8.3 36.2,78.11 36.83,78.74 | Q8.1 36.2,80.64 36.83,81.28 | Q4.1 117.47,88.27 118.11,87.63 | Q4.3 117.47,85.72 118.11,85.09 | Q2.3 117.47,74.3 118.11,73.66 | Q2.1 117.47,76.83 118.11,76.2
  Top 1.676: 35.56,46.99 35.56,44.45 35.56,41.91 41.91,41.91 45.72,45.72 C7.2 | IC7.1 17.78,95.25 20.32,97.79 | 20.32,97.79 27.94,97.79 | 27.94,97.79 29.21,96.52 29.21,88.9 36.83,81.28 36.83,78.74 | C6.2 16.51,60.96 C2.2 | C5.2 118.11,64.77 118.11,73.66 118.11,76.2 118.11,85.09 118.11,87.63 v118.11,91.44 | 27.94,97.79 29.21,99.06 v35.56,99.06 | 20.32,97.79 20.32,100.33 19.05,101.6 v17.78,101.6
  Top 2.184: POWER.3 22.55,9.2 21.59,10.16 C3.2 C1.1
  Bottom 0.406: 54.61,35.56 IC4.3 | 54.61,35.56 55.88,34.29 55.88,19.05 71.12,19.05 72.39,20.32 72.39,26.67 73.66,27.94 IC3.3 | 54.61,35.56 54.61,40.64 IC4.16 | IC3.16 86.36,33.02 C4.2 | IC5.1 17.78,55.88 19.05,57.15 C2.2 | Q1.3 32.38,57.78 33.02,58.42 | Q1.1 34.92,57.78 34.29,58.42 | Q3.3 83.19,81.92 82.55,82.55 | Q3.1 83.19,84.45 82.55,85.09 | IC8.14 26.67,13.97 24.13,16.51 C3.2 | Q7.3 36.2,94.61 36.83,93.98 | Q7.1 36.2,92.08 36.83,91.44 | Q6.3 36.2,87 36.83,86.36 | Q6.1 36.2,84.45 36.83,83.82 | 55.88,105.41 55.88,110.49 52.07,114.3 30.48,114.3 v17.78,101.6
  Bottom 1.422: 17.78,99.06 IC7.1
  Bottom 1.676: 54.61,40.64 54.61,44.45 52.07,44.45 50.8,45.72 C7.2 48.26,55.88 45.72,58.42 34.29,58.42 33.02,58.42 27.94,58.42 25.4,60.96 20.32,60.96 19.05,59.69 C2.2 | 11.43,64.77 C6.2 | v118.11,91.44 116.84,90.17 106.68,90.17 102.87,86.36 IC6.1 83.82,86.36 82.55,85.09 82.55,82.55 82.55,78.74 81.28,77.47 54.61,77.47 52.07,80.01 39.37,80.01 36.83,82.55 36.83,83.82 36.83,86.36 36.83,91.44 36.83,93.98 36.83,97.79 v35.56,99.06
  Bottom 2.184: 17.78,99.06 v17.78,101.6 13.97,101.6 11.43,99.06 11.43,64.77
  Bottom 2.54: 11.43,64.77 11.43,34.29 21.59,25.4 C3.2
  pour Bottom: 8.89,124.46 173.99,124.46 173.99,44.45 157.48,44.45 148.59,53.34 115.57,15.24 107.95,15.24 107.95,36.83 82.55,62.23 77.47,62.23 63.5,48.26 63.5,41.91 60.96,39.37 55.88,39.37 54.61,40.64 54.61,44.45 50.8,45.72 48.26,45.72 48.26,55.88 45.72,58.42 35.56,58.42 30.48,63.5 19.05,63.5 10.16,54.61 10.16,101.6 8.89,101.6
  pour Top: 8.89,124.46 175.26,124.46 175.26,0 116.84,0 116.84,41.91 102.87,55.88 102.87,72.39 58.42,72.39 58.42,71.12 8.89,71.12
W1A
  Bottom 0.406: IC3.13 86.36,25.4 IC1.1
W1B
  Bottom 0.406: IC3.12 86.36,22.86 IC1.2
W1C
  Bottom 0.406: IC3.11 86.36,20.32 IC1.3
W1D
  Bottom 0.406: IC3.10 86.36,17.78 IC1.4
W1E
  Bottom 0.406: IC3.9 86.36,15.24 IC1.5
W1F
  Bottom 0.406: IC3.15 86.36,30.48 95.25,39.37 99.06,39.37 100.33,38.1 100.33,21.59 97.79,19.05 95.25,19.05 95.25,21.59 IC1.6
W1G
  Bottom 0.406: IC3.14 86.36,27.94 96.52,38.1 97.79,38.1 99.06,36.83 99.06,22.86 IC1.7
W2A
  Bottom 0.406: IC4.13 62.23,35.56 62.23,48.26 74.93,60.96 IC2.1
W2B
  Bottom 0.406: IC4.12 63.5,34.29 63.5,46.99 74.93,58.42 IC2.2
W2C
  Bottom 0.406: IC4.11 64.77,33.02 64.77,45.72 74.93,55.88 IC2.3
W2D
  Bottom 0.406: IC4.10 66.04,31.75 66.04,44.45 74.93,53.34 IC2.4
W2E
  Bottom 0.406: IC4.9 67.31,30.48 67.31,43.18 74.93,50.8 IC2.5
W2F
  Bottom 0.406: IC4.15 57.15,35.56 57.15,20.32 62.23,20.32 69.85,27.94 69.85,39.37 74.93,44.45 78.74,44.45 78.74,46.99 77.47,48.26 IC2.6
W2G
  Bottom 0.406: IC4.14 58.42,34.29 58.42,21.59 60.96,21.59 68.58,29.21 68.58,40.64 73.66,45.72 IC2.7
WSTR1
  Top 0.406: STROBE.5 12.09,46.33 15.24,43.18 IC5.5
WSTR2
  Top 0.406: STROBE.6 13.21,50.29 15.24,48.26 IC5.3
WSTR3  (via drill 0.61 pad 1.42)
  Top 0.406: STROBE.7 11.79,54.25 13.97,52.07 19.05,52.07 22.86,55.88 59.69,55.88 68.58,64.77 v69.85,64.77
  Bottom 0.406: IC6.11 105.41,73.66 104.14,72.39 77.47,72.39 v69.85,64.77
WSTR4  (via drill 0.61 pad 1.42)
  Top 0.406: STROBE.8 11.23,58.22 12.7,59.69 12.7,64.77 15.24,67.31 59.69,67.31 62.23,69.85 90.17,69.85 92.71,67.31 v92.71,64.77
  Bottom 0.406: v92.71,64.77 105.41,64.77 106.68,66.04 IC6.9
WSTR5
  Top 0.406: STROBE.9 10.11,62.18 10.16,62.23 10.16,64.77 13.97,68.58 58.42,68.58 60.96,71.12 IC6.7
WSTR6
  Top 0.406: STROBE.10 8.99,66.14 12.7,69.85 57.15,69.85 59.69,72.39 93.98,72.39 97.79,76.2 IC6.5
WSTR7
  Top 0.406: STROBE.11 10.41,70.1 11.43,71.12 55.88,71.12 58.42,73.66 90.17,73.66 97.79,81.28 IC6.3
WSTR8  (via drill 0.61 pad 1.42)
  Top 0.406: STROBE.3 14.28,38.41 15.24,39.37 20.32,39.37 22.86,36.83 27.94,36.83 27.94,41.91 22.86,41.91 20.32,44.45 16.51,44.45 16.51,46.99 27.94,46.99 30.48,49.53 39.37,49.53 41.91,52.07 72.39,52.07 74.93,54.61 86.36,54.61 87.63,55.88 v87.63,64.77
  Bottom 0.406: v87.63,64.77 88.9,64.77 91.44,62.23 106.68,62.23 109.22,64.77 109.22,80.01 107.95,81.28 IC6.14
WSTR9
  Top 0.406: STROBE.4 13.51,42.37 13.97,41.91 20.32,41.91 21.59,40.64 IC5.11
WSTR10
  Top 0.406: STROBE.2 11.58,34.44 13.97,36.83 20.32,36.83 21.59,35.56 IC5.9
WSTR11
  Top 0.406: STROBE.15 13.11,85.95 15.24,83.82 IC7.5
WSTR12
  Top 0.406: STROBE.12 27.08,74.07 27.94,74.93 27.94,76.2 26.67,77.47 24.13,77.47 22.86,78.74 22.86,80.01 24.13,81.28 IC7.11
WSTR13
  Top 0.406: STROBE.13 13.41,78.03 13.97,77.47 21.59,77.47 22.86,76.2 IC7.9
WSTR14
  Top 0.406: STROBE.17 12.8,93.88 IC7.3
WSTR15
  Top 0.406: STROBE.16 14.22,89.92 16.51,87.63 20.32,87.63 21.59,88.9 IC7.14
WSTR16
  Top 0.406: STROBE.14 11.99,81.99 15.24,78.74 IC7.7

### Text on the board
Top: 1 | 1 | 1 | Sys7_20Top | 1 | 1
Bottom: Sys7_20Bot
